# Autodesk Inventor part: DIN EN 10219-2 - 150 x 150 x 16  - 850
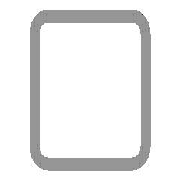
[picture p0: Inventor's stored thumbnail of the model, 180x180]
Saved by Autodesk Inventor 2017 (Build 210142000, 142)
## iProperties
Created: 2016-02
Part Number: DIN EN 10219-2 - 150 x 150 x 16  - 850
Material: Steel, Mild
Description: Cold formed welded structural hollow sections of non-alloy and fine grain structural steel
Document SubType Name: Modeling
Standard: DIN
Designer: iusti
Standard Revision: 2006-07
Standards Organization: DIN
Language: en-US
Size Designation: 150 x 150 x 16
Categories: <MemberInstance><Categories><Category DisplayName="Structural Shapes" InternalName="089c4875-fa83-4c05-b084-43b9cc11f5ed" Mnemonic="GRDR"><CategoryParameter Dis
Stock Number: 150 x 150 x 16
Mass: 49891.9 g
Surface Area: 8094.11 cm^2
Volume: 6355.65 cm^3
Density: 7.85 g/cm^3
Appearance: Semi-Polished
_CCFamilyMember: 76
_CCFamilyDisplayName: DIN EN 10219-2 (Square Hollow Section - Cold Formed) - Cold formed welded structural hollow sections of non-alloy and fine grain structural steel
_FrameMemberDoc: Frame Member File
_Version: 15.0.0
_GetPNFromCC: 1
IsCustomPart: 1
G_L: 850.000 mm
G_W: 150.000 mm
G_H: 150.000 mm
+D725846C-1BBA-43C5-9142-E43B5E702370+CUTDETAIL1: Cut
+61ECF291-9442-4532-A0A0-FF6287E9C23A+CUTDETAIL2: Cut
Author: iusti
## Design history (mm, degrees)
node "Start plane"
node "End plane"
sketch "Sketch"
  geometry: L1 (-75, -27)-(-75, 27); L2 (-27, 75)-(27, 75); L3 (75, 27)-(75, -27); L4 (27, -75)-(-27, -75); L5 (-27, 59)-(27, 59); L6 (59, 27)-(59, -27); L7 (27, -59)-(-27, -59); L8 (-59, -27)-(-59, 27); L9 (0, 118.918)-(0, -118.918) reference; L10 (-118.918, 0)-(118.918, 0) reference; A1 r 48 centre (-27, -27) between (-75, -27) and (-27, -75); A2 r 48 centre (-27, 27) between (-27, 75) and (-75, 27); A3 r 48 centre (27, 27) between (75, 27) and (27, 75); A4 r 48 centre (27, -27) between (27, -75) and (75, -27); A5 r 32 centre (-27, 27) between (-27, 59) and (-59, 27); A6 r 32 centre (27, 27) between (59, 27) and (27, 59); A7 r 32 centre (27, -27) between (27, -59) and (59, -27); A8 r 32 centre (-27, -27) between (-59, -27) and (-27, -59)
  constraints: 16 end point, 16 point on circle, 8 centre point, 8 tangent, 4 parallel, 3 equal radius, 2 perpendicular, 7 other
  dimensions: "d7" = 48 radius of A1 (= G_IR); "d10" = 150 distance between parallel lines of L2 L4 (= G_H); "d11" = 150 distance between parallel lines of L1 L3 (= G_W); "d12" = 16 distance between parallel lines of L3 L6 (= G_T); "d15" = 75 distance between parallel lines of L2 L10 (= 0.5 x d10); "d16" = 75 distance between parallel lines of L9 L3 (= 0.5 x d11)
extrude "Body" new body sketch "Sketch" stored distance "d3" = 850 (= G_L); taper "d4" = 0 deg
node "Driven Length"
  sketch "Sketch3"
    geometry: L1 (0, 0)-(10, 0) reference
    constraints: 2 end point, 1 horizontal
  workplane "Work Plane3"
  sketch "Sketch4"
    geometry: L1 (-2, 75)-(12, 75) reference; L2 (-2, 925)-(12, 925) reference
    dimensions: "d18" = 850 distance between parallel lines of L1 L2 (derived)
workplane "Work Plane4"
split "Split1"
workplane "Work Plane5"
split "Split2"
body "Solid1"
other parameters: "G_W" = 150 [user parameter; used in 1 equation term], "G_H" = 150 [user parameter; used in 1 equation term], "G_T" = 16 [user parameter; used in 1 equation term], "G_IR" = 48 [user parameter; used in 1 equation term], "G_L" = 850 (= d18) [user parameter; used in 1 equation term], "G_OFFSET_START" = -75 [user parameter; used in 1 equation term], "G_OFFSET_END" = -75 [user parameter; used in 1 equation term], "d13" = 75 (= -G_OFFSET_START), "d14" = 925 (= G_OFFSET_END + B_L), "d17" = 90 deg
